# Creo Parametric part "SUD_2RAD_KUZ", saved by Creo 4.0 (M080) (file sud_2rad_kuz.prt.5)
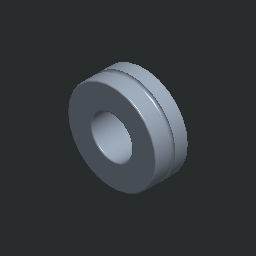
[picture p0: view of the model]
Units: millimeter Kilogram Sec (mmKs); MM, KILOGRAM, SECS
Materials in the file: OCEL_N

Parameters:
  MFG_WP_MATERIAL = "RO6_8"
  NAZOV = "SUD_2RAD_KUZ"
  PTC_MATERIAL_NAME = "OCEL_N"

Other parameters: HMOTNOST, HUSTOTA, D17

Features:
  1. datum plane "DTM2"
  2. cut
  3. cut
  4. round

Layers: 1, 2, 3, 4, 5, 6, 7, 8, 9, 10, 11, 12, 13, 14, 15, 16, 17, 18, 19, 20, 21, 22, 23, 24, 25, 26, 27, 28, 29, 30, 31, 32

Family table entries: GENERIC, LOZISKO_22308KJ, SUD_2RAD_KUZ, value(d_val), value(i_val), LOZISKO_22309KJ, SUD_2RAD_KUZ, 2/Y, 2/B, LOZISKO_22310KJ, SUD_2RAD_KUZ, !/I, 2/D, LOZISKO_22311KJ, SUD_2RAD_KUZ, 2/^, LOZISKO_22312KJ, SUD_2RAD_KUZ, !/N, 2/G, LOZISKO_22313KM, SUD_2RAD_KUZ, 2/H, LOZISKO_22214KJ, SUD_2RAD_KUZ, 2/?, LOZISKO_22314KJ, SUD_2RAD_KUZ, LOZISKO_22215KJ, SUD_2RAD_KUZ, 2/?, LOZISKO_22315KJ, SUD_2RAD_KUZ, 2/d, LOZISKO_22216KJ, SUD_2RAD_KUZ, !/T, LOZISKO_22316KJ, SUD_2RAD_KUZ, !/T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

Surfaces: 10 torus, 2 plane, 2 cone, 1 cylinder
